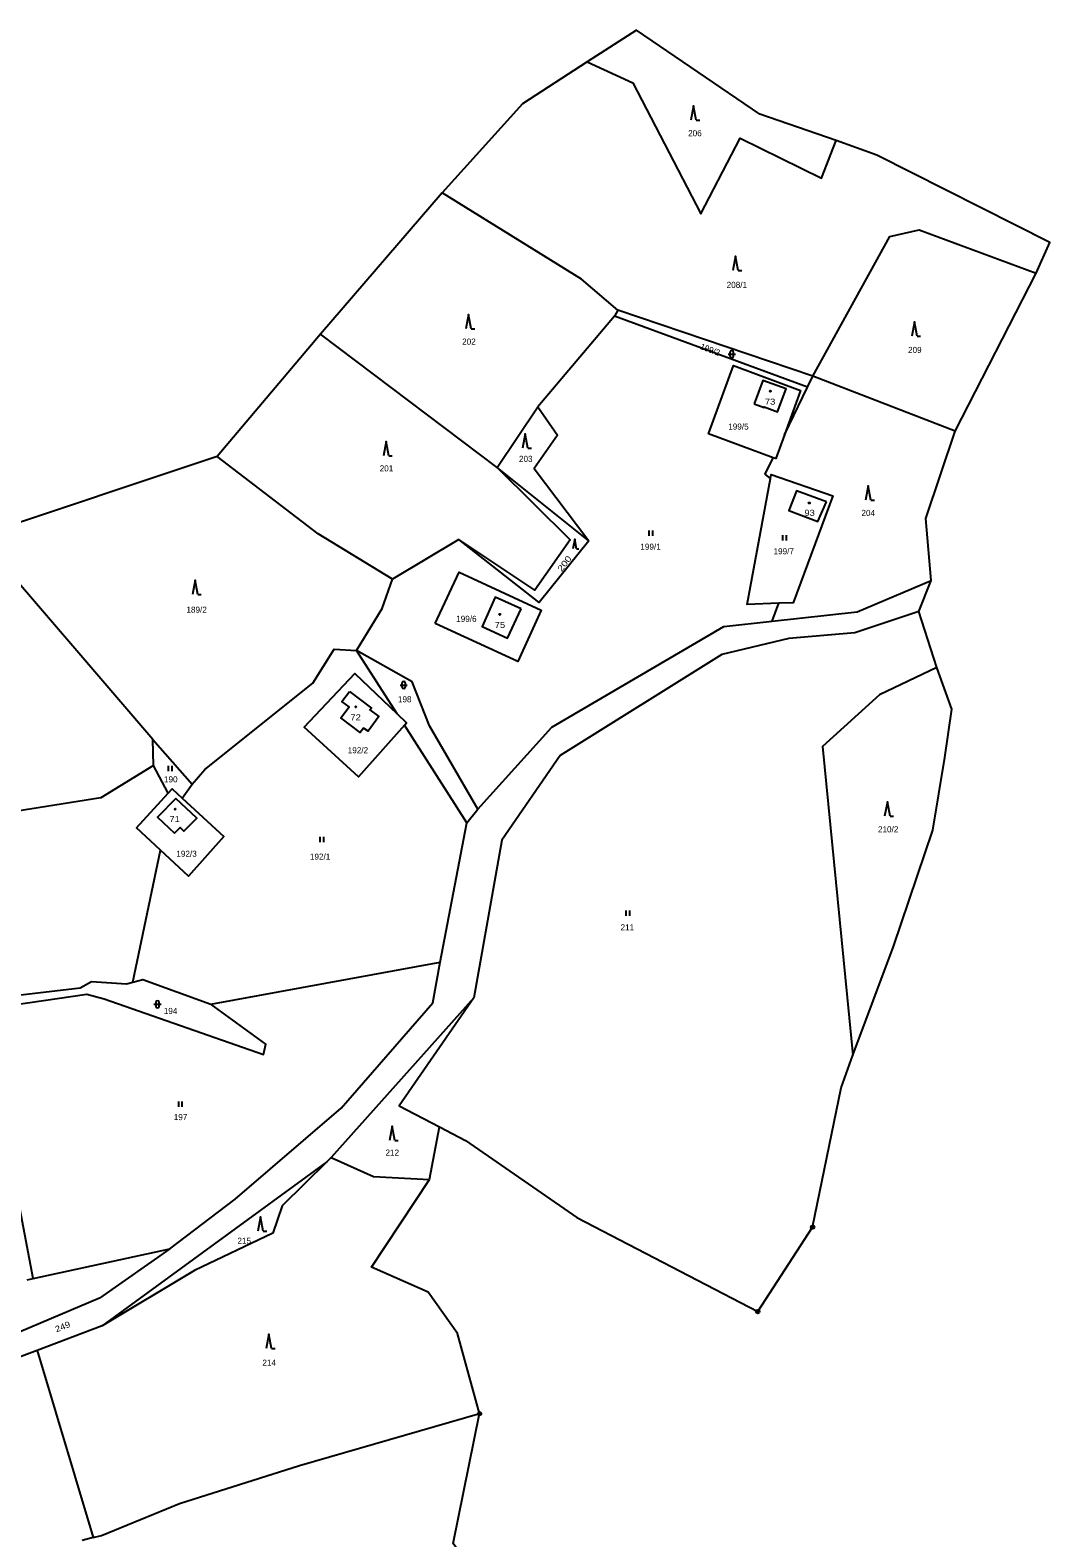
# Model space of a CAD drawing. Extents: x -632162 to -629607, y -1101195 to -1098670.
# Drawn here: x -631040.8 to -630756.2, y -1099752.9 to -1099332 of the extents above; entities that cross this region are included whole.
import ezdxf
from ezdxf.enums import TextEntityAlignment as Align

# ---------------------------------------------------------------- set-up
doc = ezdxf.new("R2010")
doc.units = 0
doc.header["$LTSCALE"] = 0.68
for name, color, linetype, lineweight in [('1', 7, 'Continuous', 25), ('3', 7, 'Continuous', 25), ('5', 7, 'Continuous', 25), ('8', 7, 'Continuous', 25)]:
    doc.layers.add(name, color=color, linetype=linetype, lineweight=lineweight)
doc.layers.add('2', color=7, linetype='Continuous')

msp = doc.modelspace()

# ---------------------------------------------------------------- linework, layer by layer
at = {"layer": '1'}
for p, q in [((-630782.61, -1099443.94), (-630760.07, -1099399.84)), ((-630959.77, -1099416.91), (-630988.58, -1099451.03)), ((-630910.45, -1099454.15), (-630959.77, -1099416.91)), ((-630823.82, -1099431.67), (-630822.32, -1099428.58)), ((-630910.45, -1099454.15), (-630899.15, -1099437.15)), ((-630884.93, -1099474.6), (-630910.45, -1099454.15)), ((-630792.76, -1099494.33), (-630789.37, -1099485.64)), ((-630938.38, -1099522.86), (-630949.7, -1099505.16)), ((-631006.59, -1099530.01), (-630995.57, -1099542.49)), ((-630998.37, -1099546.42), (-630995.57, -1099542.49)), ((-630918.94, -1099553.26), (-630915.87, -1099549.44)), ((-630916.96, -1099602.16), (-630956.82, -1099646.67)), ((-630929.4, -1099652.85), (-630926.54, -1099638.11)), ((-630958.05, -1099647.95), (-631020.7, -1099693.68)), ((-630956.82, -1099646.67), (-630958.05, -1099647.95)), ((-631039.98, -1099680.51), (-631001.85, -1099672.16)), ((-631041.67, -1099680.85), (-631039.98, -1099680.51)), ((-631038.83, -1099700.55), (-631052.81, -1099705.81)), ((-631023.23, -1099752.8), (-631026.33, -1099753.56))]:
    msp.add_line(p, q, dxfattribs=at)
for points in [[(-630815.87, -1099362.85), (-630837.14, -1099355.52), (-630871.59, -1099332.04), (-630885.37, -1099340.91)], [(-630885.37, -1099340.91), (-630903.42, -1099352.61), (-630925.83, -1099377.45)], [(-630885.37, -1099340.91), (-630872.6, -1099346.72), (-630853.66, -1099383.35), (-630842.64, -1099362.17), (-630819.95, -1099373.31), (-630815.87, -1099362.85)], [(-630760.07, -1099399.84), (-630756.21, -1099391.29), (-630804.49, -1099366.97), (-630815.87, -1099362.85)], [(-630876.77, -1099410.21), (-630886.98, -1099401.52), (-630925.83, -1099377.45), (-630959.77, -1099416.91)], [(-630822.32, -1099428.58), (-630800.91, -1099389.65), (-630792.7, -1099387.8), (-630760.07, -1099399.84)], [(-630830.29, -1099444.98), (-630823.82, -1099431.67), (-630877.72, -1099411.9), (-630899.15, -1099437.15)], [(-630822.32, -1099428.58), (-630876.77, -1099410.21), (-630877.72, -1099411.9)], [(-630833.4, -1099451.38), (-630851.45, -1099444.67), (-630844.51, -1099425.68), (-630825.78, -1099432.64), (-630830.29, -1099444.98)], [(-630789.37, -1099485.64), (-630790.85, -1099468.37), (-630782.61, -1099443.94), (-630822.32, -1099428.58)], [(-630899.15, -1099437.15), (-630893.61, -1099445.05), (-630900.18, -1099454.38), (-630884.93, -1099474.6)], [(-630830.29, -1099444.98), (-630832.72, -1099451.63), (-630833.4, -1099451.38)], [(-630939.7, -1099485.24), (-630960.44, -1099472.59), (-630988.58, -1099451.03), (-631055.38, -1099473.27)], [(-630834.19, -1099457.16), (-630835.64, -1099456), (-630833.4, -1099451.38)], [(-630910.45, -1099454.15), (-630890.12, -1099474.28), (-630899.99, -1099488.34), (-630921.14, -1099474.24)], [(-630831.84, -1099492.02), (-630840.73, -1099492.34), (-630834.19, -1099457.16)], [(-630834.19, -1099457.16), (-630833.99, -1099456.1), (-630816.79, -1099461.99), (-630827.86, -1099491.87), (-630831.84, -1099492.02)], [(-631006.36, -1099537.27), (-631006.59, -1099530.01), (-631055.38, -1099473.27)], [(-630884.93, -1099474.6), (-630898.78, -1099491.83), (-630921.14, -1099474.24), (-630939.7, -1099485.24)], [(-630949.7, -1099505.16), (-630942.61, -1099493.45), (-630939.7, -1099485.24)], [(-630833.68, -1099497.04), (-630809.97, -1099494.44), (-630789.37, -1099485.64)], [(-630915.87, -1099549.44), (-630895.24, -1099526.59), (-630847.25, -1099498.53), (-630833.68, -1099497.04), (-630831.84, -1099492.02)], [(-630792.76, -1099494.33), (-630810.68, -1099500.28), (-630829.05, -1099501.86), (-630847.72, -1099506.29), (-630892.88, -1099534.54), (-630909.19, -1099558.13), (-630916.96, -1099602.16)], [(-630811.21, -1099618.16), (-630799.81, -1099587.79), (-630788.87, -1099555.3), (-630785.56, -1099535.07), (-630783.59, -1099521.58), (-630787.78, -1099509.98), (-630792.76, -1099494.33)], [(-631006.36, -1099537.27), (-631021.08, -1099546.27), (-631059.67, -1099552.5), (-631091.14, -1099498.92)], [(-630995.57, -1099542.49), (-630992.08, -1099538.37), (-630961.89, -1099514.28), (-630955.99, -1099504.8), (-630949.7, -1099505.16)], [(-630915.87, -1099549.44), (-630929.33, -1099526.23), (-630934.23, -1099513.89), (-630949.7, -1099505.16)], [(-630787.78, -1099509.98), (-630803.72, -1099517.59), (-630819.62, -1099531.95), (-630811.21, -1099618.16)], [(-630936.36, -1099526.02), (-630949.21, -1099540.45), (-630964.37, -1099526.55), (-630950.22, -1099511.58), (-630938.38, -1099522.86)], [(-630936.36, -1099526.02), (-630935.76, -1099525.35), (-630938.38, -1099522.86)], [(-631012.14, -1099597.76), (-631009.37, -1099597.03), (-630990.44, -1099603.92), (-630926.35, -1099592.15), (-630918.94, -1099553.26), (-630936.36, -1099526.02)], [(-631004.42, -1099560.95), (-631011.18, -1099554.65), (-631002.28, -1099545.03), (-631006.36, -1099537.27)], [(-631002.28, -1099545.03), (-631001.18, -1099543.84), (-630998.37, -1099546.42)], [(-630998.37, -1099546.42), (-630986.74, -1099557.09), (-630996.65, -1099568.2), (-631004.42, -1099560.95)], [(-631052.93, -1099633.96), (-631064.19, -1099605.09), (-631056.15, -1099602.76), (-631026.83, -1099599.37), (-631023.66, -1099597.58), (-631013.93, -1099598.2), (-631012.14, -1099597.76), (-631004.42, -1099560.95)], [(-631001.85, -1099672.16), (-630983.63, -1099658.35), (-630953.99, -1099632.92), (-630928.44, -1099603.57), (-630926.35, -1099592.15)], [(-631039.98, -1099680.51), (-631047.72, -1099639.68), (-631061.37, -1099606.43), (-631024.96, -1099601.16), (-631020.15, -1099602.42), (-630975.74, -1099617.95), (-630975.07, -1099615.11), (-630990.44, -1099603.92)], [(-630916.96, -1099602.16), (-630937.86, -1099632.32), (-630926.54, -1099638.11)], [(-630926.54, -1099638.11), (-630919.33, -1099641.96), (-630888.21, -1099663.45), (-630837.73, -1099689.71), (-630822.43, -1099666.14), (-630814.46, -1099627.25), (-630811.21, -1099618.16)], [(-630958.05, -1099647.95), (-630970.51, -1099660.18), (-630973.06, -1099667.83), (-630994.95, -1099678.23), (-631020.7, -1099693.68)], [(-630956.82, -1099646.67), (-630945.01, -1099651.98), (-630929.4, -1099652.85)], [(-630915.37, -1099718.19), (-630921.57, -1099695.87), (-630929.69, -1099684.31), (-630945.58, -1099677.3), (-630929.4, -1099652.85)], [(-631001.85, -1099672.16), (-631021.44, -1099685.96), (-631093.61, -1099716.5), (-631142.66, -1099741.51), (-631259.83, -1099801.22)], [(-631020.7, -1099693.68), (-631038.83, -1099700.55), (-631023.23, -1099752.8)], [(-631023.23, -1099752.8), (-631020.89, -1099752.22), (-630999.18, -1099743.29), (-630965.66, -1099732.67), (-630915.37, -1099718.19)], [(-630930.38, -1099826.1), (-630902.71, -1099804.02), (-630906.25, -1099791.11), (-630914.09, -1099782.13), (-630910.06, -1099768.89), (-630914.18, -1099766.08), (-630922.77, -1099754.42), (-630915.37, -1099718.19)]]:
    msp.add_lwpolyline(points, dxfattribs=at)
for points in [[(-630838.77, -1099436.33), (-630835.98, -1099437.38), (-630835.91, -1099437.19), (-630832.2, -1099438.58), (-630829.81, -1099432.19), (-630836.33, -1099429.81)], [(-630818.54, -1099463.73), (-630826.88, -1099460.67), (-630829.04, -1099466.08), (-630820.94, -1099469.16)], [(-630927.82, -1099497.7), (-630921.1, -1099483.28), (-630898.17, -1099493.92), (-630904.74, -1099508.25)], [(-630903.82, -1099493.57), (-630911.03, -1099490.29), (-630914.68, -1099498.5), (-630907.6, -1099501.72)], [(-630951.71, -1099516.68), (-630945.57, -1099521.25), (-630945.98, -1099521.76), (-630943.5, -1099523.62), (-630946.51, -1099527.71), (-630947.77, -1099526.85), (-630948.74, -1099528.04), (-630954.08, -1099524.02), (-630951.75, -1099520.95), (-630953.8, -1099519.39)], [(-631000.5, -1099556.21), (-630998.97, -1099554.59), (-630997.95, -1099555.63), (-630994.33, -1099551.95), (-631000.18, -1099546.46), (-631005.25, -1099551.68)]]:
    msp.add_lwpolyline(points, close=True, dxfattribs=at)
at = {"layer": '3'}
for p, q in [((-630854.92, -1099357.17), (-630853.924, -1099357.17)), ((-630843.2, -1099399.08), (-630842.204, -1099399.08)), ((-630917.74, -1099415.44), (-630916.744, -1099415.44)), ((-630793.27, -1099417.49), (-630792.274, -1099417.49)), ((-630845.491, -1099421.981), (-630845.491, -1099422.982)), ((-630844.489, -1099422.982), (-630844.489, -1099421.981)), ((-630845.991, -1099422.481), (-630843.989, -1099422.481)), ((-630940.74, -1099450.83), (-630939.744, -1099450.83)), ((-630901.93, -1099448.74), (-630900.934, -1099448.74)), ((-630806.15, -1099463.23), (-630805.154, -1099463.23)), ((-630868.001, -1099473.22), (-630868.001, -1099471.72)), ((-630867, -1099473.22), (-630867, -1099471.72)), ((-630830.731, -1099474.51), (-630830.731, -1099473.01)), ((-630829.73, -1099474.51), (-630829.73, -1099473.01)), ((-630888.318, -1099476.83), (-630887.65, -1099476.83)), ((-630994.05, -1099489.54), (-630993.054, -1099489.54)), ((-630937.071, -1099514.321), (-630937.071, -1099515.322)), ((-630936.069, -1099515.322), (-630936.069, -1099514.321)), ((-630937.571, -1099514.821), (-630935.569, -1099514.821)), ((-631002.231, -1099538.9), (-631002.231, -1099537.4)), ((-631001.23, -1099538.9), (-631001.23, -1099537.4)), ((-630800.82, -1099551.45), (-630799.824, -1099551.45)), ((-630959.901, -1099558.73), (-630959.901, -1099557.23)), ((-630958.9, -1099558.73), (-630958.9, -1099557.23)), ((-630874.431, -1099579.27), (-630874.431, -1099577.77)), ((-630873.43, -1099579.27), (-630873.43, -1099577.77)), ((-631006.291, -1099603.941), (-631004.289, -1099603.941)), ((-631005.791, -1099603.441), (-631005.791, -1099604.442)), ((-631004.789, -1099604.442), (-631004.789, -1099603.441)), ((-630999.351, -1099632.57), (-630999.351, -1099631.07)), ((-630998.35, -1099632.57), (-630998.35, -1099631.07)), ((-630939.06, -1099641.96), (-630938.064, -1099641.96)), ((-630975.75, -1099667.31), (-630974.754, -1099667.31)), ((-630973.42, -1099700.03), (-630972.424, -1099700.03))]:
    msp.add_line(p, q, dxfattribs=at)
for points in [[(-630854.92, -1099357.17), (-630855.67, -1099353.17), (-630856.42, -1099357.17)], [(-630843.2, -1099399.08), (-630843.95, -1099395.08), (-630844.7, -1099399.08)], [(-630917.74, -1099415.44), (-630918.49, -1099411.44), (-630919.24, -1099415.44)], [(-630793.27, -1099417.49), (-630794.02, -1099413.49), (-630794.77, -1099417.49)], [(-630940.74, -1099450.83), (-630941.49, -1099446.83), (-630942.24, -1099450.83)], [(-630901.93, -1099448.74), (-630902.68, -1099444.74), (-630903.43, -1099448.74)], [(-630806.15, -1099463.23), (-630806.9, -1099459.23), (-630807.65, -1099463.23)], [(-630888.318, -1099476.83), (-630888.82, -1099474.15), (-630889.322, -1099476.83)], [(-630994.05, -1099489.54), (-630994.8, -1099485.54), (-630995.55, -1099489.54)], [(-630800.82, -1099551.45), (-630801.57, -1099547.45), (-630802.32, -1099551.45)], [(-630939.06, -1099641.96), (-630939.81, -1099637.96), (-630940.56, -1099641.96)], [(-630975.75, -1099667.31), (-630976.5, -1099663.31), (-630977.25, -1099667.31)], [(-630973.42, -1099700.03), (-630974.17, -1099696.03), (-630974.92, -1099700.03)]]:
    msp.add_lwpolyline(points, dxfattribs=at)
for centre, start, end in [((-630844.99, -1099421.9809), 0, 180), ((-630844.99, -1099422.9809), 180, 359.98789), ((-630936.57, -1099514.3209), 0, 180), ((-630936.57, -1099515.3209), 180, 359.98789), ((-631005.29, -1099603.4409), 0, 180), ((-631005.29, -1099604.4409), 180, 359.98789)]:
    msp.add_arc(centre, 0.5, start, end, dxfattribs=at)
at = {"layer": '5'}
for centre in [(-630834.2468, -1099432.7992), (-630823.3568, -1099464.0292), (-630909.7268, -1099495.1192), (-630949.9168, -1099520.9092), (-631000.3468, -1099549.4892)]:
    msp.add_circle(centre, 0.175, dxfattribs=at)
at = {"layer": '8'}
for centre, radius in [((-630822.43, -1099666.1399), 0.5), ((-630822.43, -1099666.1399), 0.0303), ((-630837.73, -1099689.7099), 0.5), ((-630837.73, -1099689.7099), 0.0303), ((-630915.37, -1099718.1899), 0.5), ((-630915.37, -1099718.1899), 0.0303)]:
    msp.add_circle(centre, radius, dxfattribs=at)

# ---------------------------------------------------------------- texts
at = {"layer": '2'}
for s, p in [('206', (-630855.269, -1099361.65)), ('208/1', (-630843.57, -1099403.99)), ('202', (-630918.349, -1099419.82)), ('209', (-630793.899, -1099422.15)), ('199/5', (-630843.13, -1099443.54)), ('203', (-630902.489, -1099452.55)), ('201', (-630941.369, -1099455.2)), ('204', (-630806.899, -1099467.64)), ('199/1', (-630867.66, -1099477.06)), ('199/7', (-630830.49, -1099478.34)), ('189/2', (-630994.36, -1099494.65)), ('199/6', (-630919.06, -1099497.2)), ('198', (-630936.279, -1099519.64)), ('192/2', (-630949.34, -1099533.88)), ('190', (-631001.569, -1099542)), ('210/2', (-630801.34, -1099555.95)), ('192/3', (-630997.17, -1099562.77)), ('192/1', (-630959.9, -1099563.58)), ('211', (-630874.139, -1099583.31)), ('194', (-631001.629, -1099606.64)), ('197', (-630998.839, -1099636.28)), ('212', (-630939.749, -1099646.19)), ('215', (-630981.069, -1099670.79)), ('214', (-630974.109, -1099704.83))]:
    msp.add_text(s, height=1.7, dxfattribs=at).set_placement(p, align=Align.CENTER)
msp.add_text('199/2', height=1.7, rotation=339, dxfattribs=at).set_placement((-630851.3306, -1099421.9909), align=Align.CENTER)
at = {"layer": '2', "width": 1.15}
for s, p in [('73', (-630834.29, -1099436.58)), ('93', (-630823.26, -1099467.61)), ('75', (-630909.7, -1099498.91)), ('72', (-630949.98, -1099524.7)), ('71', (-631000.5, -1099553.1))]:
    msp.add_text(s, height=1.7, dxfattribs=at).set_placement(p, align=Align.CENTER)
at = {"layer": '2'}
for s, rotation, width, p in [('200', 53, 1.25, (-630891.0033, -1099481.4295)), ('249', 22, 1.15, (-631031.4489, -1099694.7115))]:
    msp.add_text(s, height=1.7, rotation=rotation, dxfattribs=dict(at, width=width)).set_placement(p, align=Align.CENTER)

doc.saveas('drawing.dxf')
